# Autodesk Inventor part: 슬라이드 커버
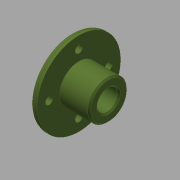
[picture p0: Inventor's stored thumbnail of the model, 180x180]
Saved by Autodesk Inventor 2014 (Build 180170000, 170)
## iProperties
Created: 2015-12
Part Number: 슬라이드 커버
Document SubType Name: Modeling
Designer: mdu
Density: 2.71 g/cm^3
Material: 알루미늄 6061
Appearance: 알루미늄 - 평지
Mass: 49.5251 g
Surface Area: 80.5945 cm^2
Volume: 18.2749 cm^3
Author: mdu
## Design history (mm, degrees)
sketch "스케치1"
  geometry: L1 (-12.5, 0)-(12.5, 0); L2 (-12.5, 0)-(-12.5, 28); L3 (-12.5, 28)-(-7.5, 28); L4 (-7.5, 28)-(-7.5, 13); L5 (-7.5, 13)-(12.5, 13); L6 (12.5, 13)-(12.5, 0); 2 further points
  constraints: 12 end point, 3 perpendicular, 1 coincident, 1 horizontal, 1 midpoint, 1 parallel
  dimensions: "d1" = 56 diameter of L3 L1; "d2" = 26 diameter of L5 L1; "d5" = 5 distance of L2.end L3.end; "d32" = 20 distance of L4.end L5.end
revolve "회전1" sketch "스케치1" stored, may be unused: angle "d6" = 90 deg
sketch "스케치2" dims "d33" = 40
  geometry: 3 further points
  constraints: 2 vertical alignment, 1 coincident, 2 other
hole "구멍1" sketch "스케치2" at (0, 20) diameter "d8" = 5; stored, may be unused: countersink angle "d12" = 90 deg, drill point angle "d14" = 118 deg; dims "d9" = 6, "d10" = 8, "d11" = 4.4, "d13" = 8
hole "구멍2" diameter "d20" = 14; stored, may be unused: countersink angle "d24" = 90 deg, drill point angle "d26" = 0 deg; dims "d18" = 10, "d19" = 10, "d21" = 6, "d22" = 8, "d23" = 4.4, "d25" = 8
fillet "모깎기1" dims "d27" = 3
chamfer "모따기1" distance "d29" = 1; stored, may be unused: second distance "d30" = 2, angle "d31" = 45 deg
node "솔리드1"
pattern_circular "원형 패턴1" dims angle "d16" = 360 deg
